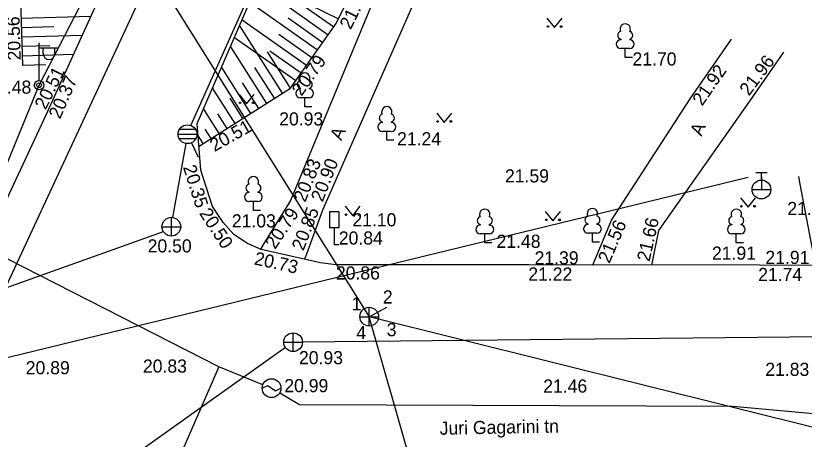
# Model space of a CAD drawing. Extents: x 714391 to 714584, y 6589993 to 6590151.
# Drawn here: x 714448.93 to 714490.89, y 6590092.2 to 6590114.75 of the extents above; entities that cross this region are included whole.
import ezdxf

# ---------------------------------------------------------------- set-up
doc = ezdxf.new("R2010")
doc.units = 0
for name, color, linetype in [('HALJASTUS', 7, 'Continuous'), ('HOONE', 7, 'Continuous'), ('KKAEV', 7, 'Continuous'), ('KORGUS', 7, 'Continuous'), ('KTRASS', 7, 'Continuous'), ('LIIKLUS', 7, 'Continuous'), ('MPKAABEL', 7, 'Continuous'), ('POST', 7, 'Continuous'), ('PUU', 7, 'Continuous'), ('RELJEEF', 7, 'Continuous'), ('SITRASS', 7, 'Continuous'), ('SKKAEV', 7, 'Continuous'), ('SKTRASS', 7, 'Continuous'), ('TEE', 7, 'Continuous'), ('TORU NR', 7, 'Continuous'), ('VKAEV', 7, 'Continuous'), ('VTRASS', 7, 'Continuous')]:
    doc.layers.add(name, color=color, linetype=linetype)

msp = doc.modelspace()

# ---------------------------------------------------------------- linework, layer by layer
at = {"layer": 'HALJASTUS'}
for p, q in [((714477.203, 6590114.63), (714477.608, 6590114.125)), ((714477.608, 6590114.125), (714478.003, 6590114.63)), ((714460.812, 6590110.566), (714461.217, 6590110.061)), ((714461.217, 6590110.061), (714461.612, 6590110.566)), ((714471.333, 6590109.573), (714471.738, 6590109.068)), ((714471.738, 6590109.068), (714472.133, 6590109.573)), ((714487.498, 6590105.058), (714487.903, 6590104.553)), ((714487.903, 6590104.553), (714488.298, 6590105.058)), ((714466.456, 6590104.606), (714466.861, 6590104.101)), ((714466.861, 6590104.101), (714467.256, 6590104.606)), ((714477.113, 6590104.335), (714477.518, 6590103.83)), ((714477.518, 6590103.83), (714477.913, 6590104.335))]:
    msp.add_line(p, q, dxfattribs=at)
for centre, radius in [((714477.255, 6590114.18), 0.0428), ((714477.955, 6590114.18), 0.0452), ((714460.864, 6590110.117), 0.0428), ((714461.564, 6590110.117), 0.0452), ((714471.385, 6590109.123), 0.0428), ((714472.085, 6590109.123), 0.0452), ((714487.55, 6590104.608), 0.0428), ((714488.25, 6590104.608), 0.0452), ((714466.508, 6590104.156), 0.0428), ((714467.208, 6590104.156), 0.0452), ((714477.165, 6590103.885), 0.0428), ((714477.865, 6590103.885), 0.0452)]:
    msp.add_circle(centre, radius, dxfattribs=at)
at = {"layer": 'HOONE'}
for p, q in [((714462.045, 6590094.919), (714462.345, 6590095.069)), ((714462.345, 6590095.069), (714462.745, 6590094.769)), ((714462.745, 6590094.769), (714463.045, 6590094.919))]:
    msp.add_line(p, q, dxfattribs=at)
for points in [[(714462.081, 6590095.105), (714459.73, 6590096.05), (714433.74, 6590109.31), (714441.36, 6590125.77), (714449.34, 6590143.41), (714452.652, 6590151.075)], [(714459.73, 6590096.05), (714450.33, 6590074.44), (714440.46, 6590052.39), (714432.7, 6590035.24), (714421.56, 6590009.98), (714417.1, 6590000.12), (714413.783, 6589992.711)], [(714462.976, 6590094.666), (714464.039, 6590094.043), (714487.101, 6590093.963), (714494.525, 6590093.286), (714520.217, 6590091.196), (714543.829, 6590084.007)]]:
    msp.add_lwpolyline(points, dxfattribs=at)
msp.add_circle((714462.545, 6590094.919), 0.5, dxfattribs=at)
at = {"layer": 'KKAEV'}
for p, q in [((714457.21, 6590103.019), (714457.21, 6590104.019)), ((714456.71, 6590103.519), (714457.71, 6590103.519)), ((714467.741, 6590098.226), (714467.741, 6590099.226)), ((714467.241, 6590098.726), (714468.241, 6590098.726)), ((714463.689, 6590096.867), (714463.689, 6590097.867)), ((714463.189, 6590097.367), (714464.189, 6590097.367))]:
    msp.add_line(p, q, dxfattribs=at)
for centre in [(714457.21, 6590103.519), (714467.741, 6590098.726), (714463.689, 6590097.367)]:
    msp.add_circle(centre, 0.5, dxfattribs=at)
at = {"layer": 'KTRASS'}
for p, q in [((714455.022, 6590119.06), (714467.741, 6590098.726)), ((714467.741, 6590098.726), (714468.676, 6590099.236)), ((714475.96, 6590069.911), (714467.741, 6590098.726)), ((714505.642, 6590089.275), (714467.741, 6590098.726))]:
    msp.add_line(p, q, dxfattribs=at)
at = {"layer": 'LIIKLUS'}
for p, q in [((714465.62, 6590104.311), (714465.62, 6590103.461)), ((714466.12, 6590104.311), (714465.62, 6590104.311)), ((714466.12, 6590104.311), (714466.12, 6590103.461)), ((714466.12, 6590103.461), (714465.62, 6590103.461)), ((714465.87, 6590103.461), (714465.87, 6590102.561)), ((714466.12, 6590102.561), (714465.87, 6590102.561))]:
    msp.add_line(p, q, dxfattribs=at)
at = {"layer": 'MPKAABEL'}
msp.add_lwpolyline([(714394.611, 6589992.711), (714400.19, 6590004.938), (714412.114, 6590031.265), (714423.696, 6590056.183), (714434.84, 6590082.35), (714435.599, 6590083.495), (714435.59, 6590083.97), (714441.1, 6590097.08), (714442.02, 6590098.72), (714442.75, 6590099.35), (714444.22, 6590100.41), (714445.54, 6590101.3), (714446.63, 6590102.41), (714450.168, 6590111.053), (714453.153, 6590116.846), (714463.66, 6590139.57), (714466.53, 6590147), (714468.444, 6590151.075)], dxfattribs=at)
at = {"layer": 'POST'}
for p, q in [((714450.168, 6590111.303), (714450.168, 6590113.303)), ((714450.168, 6590113.053), (714451.168, 6590113.053)), ((714450.395, 6590112.732), (714450.395, 6590113.053)), ((714451.007, 6590112.732), (714451.007, 6590113.053)), ((714450.168, 6590111.053), (714450.168, 6590111.053))]:
    msp.add_line(p, q, dxfattribs=at)
for radius in [0.25, 0.127]:
    msp.add_circle((714450.168, 6590111.053), radius, dxfattribs=at)
msp.add_arc((714450.701, 6590112.732), 0.306, 180, 0, dxfattribs=at)
at = {"layer": 'PUU'}
for p, q in [((714481.126, 6590113.508), (714481.126, 6590113.478)), ((714481.606, 6590113.508), (714481.606, 6590113.478)), ((714481.606, 6590113.003), (714481.126, 6590113.003)), ((714481.366, 6590112.528), (714481.366, 6590113.003)), ((714481.746, 6590112.528), (714481.366, 6590112.528)), ((714464.069, 6590110.889), (714464.069, 6590110.859)), ((714464.549, 6590110.889), (714464.549, 6590110.859)), ((714464.549, 6590110.384), (714464.069, 6590110.384)), ((714464.309, 6590109.909), (714464.309, 6590110.384)), ((714464.689, 6590109.909), (714464.309, 6590109.909)), ((714468.438, 6590109.099), (714468.438, 6590109.069)), ((714468.918, 6590109.099), (714468.918, 6590109.069)), ((714468.918, 6590108.594), (714468.438, 6590108.594)), ((714468.678, 6590108.119), (714468.678, 6590108.594)), ((714469.058, 6590108.119), (714468.678, 6590108.119)), ((714461.337, 6590105.369), (714461.337, 6590105.339)), ((714461.817, 6590105.369), (714461.817, 6590105.339)), ((714461.817, 6590104.864), (714461.337, 6590104.864)), ((714461.577, 6590104.389), (714461.577, 6590104.864)), ((714461.957, 6590104.389), (714461.577, 6590104.389)), ((714473.652, 6590103.639), (714473.652, 6590103.609)), ((714474.132, 6590103.639), (714474.132, 6590103.609)), ((714479.381, 6590103.674), (714479.381, 6590103.644)), ((714479.861, 6590103.674), (714479.861, 6590103.644)), ((714487.037, 6590103.641), (714487.037, 6590103.611)), ((714487.517, 6590103.641), (714487.517, 6590103.611)), ((714474.132, 6590103.134), (714473.652, 6590103.134)), ((714473.892, 6590102.659), (714473.892, 6590103.134)), ((714479.861, 6590103.169), (714479.381, 6590103.169)), ((714479.621, 6590102.694), (714479.621, 6590103.169)), ((714487.517, 6590103.136), (714487.037, 6590103.136)), ((714487.277, 6590102.661), (714487.277, 6590103.136)), ((714474.272, 6590102.659), (714473.892, 6590102.659)), ((714480.001, 6590102.694), (714479.621, 6590102.694)), ((714487.657, 6590102.661), (714487.277, 6590102.661))]:
    msp.add_line(p, q, dxfattribs=at)
for centre, radius, start, end in [((714481.366, 6590114.048), 0.277, 332.5799, 207.4201), ((714481.176, 6590113.715), 0.212, 105.2441, 257.079), ((714481.556, 6590113.715), 0.212, 282.921, 74.7559), ((714481.128, 6590113.24), 0.237, 90, 270), ((714481.603, 6590113.24), 0.237, 270, 90), ((714464.309, 6590111.429), 0.277, 332.5799, 207.4201), ((714464.119, 6590111.096), 0.212, 105.2441, 257.079), ((714464.499, 6590111.096), 0.212, 282.921, 74.7559), ((714464.071, 6590110.622), 0.237, 90, 270), ((714464.546, 6590110.622), 0.237, 270, 90), ((714468.488, 6590109.306), 0.212, 105.2441, 257.079), ((714468.678, 6590109.639), 0.277, 332.5799, 207.4201), ((714468.868, 6590109.306), 0.212, 282.921, 74.7559), ((714468.441, 6590108.832), 0.237, 90, 270), ((714468.916, 6590108.832), 0.237, 270, 90), ((714461.577, 6590105.909), 0.277, 332.5799, 207.4201), ((714461.387, 6590105.577), 0.212, 105.2441, 257.079), ((714461.767, 6590105.577), 0.212, 282.921, 74.7559), ((714461.34, 6590105.102), 0.237, 90, 270), ((714461.815, 6590105.102), 0.237, 270, 90), ((714479.621, 6590104.214), 0.277, 332.5799, 207.4201), ((714473.892, 6590104.179), 0.277, 332.5799, 207.4201), ((714479.431, 6590103.882), 0.212, 105.2441, 257.079), ((714479.811, 6590103.882), 0.212, 282.921, 74.7559), ((714487.277, 6590104.181), 0.277, 332.5799, 207.4201), ((714473.702, 6590103.846), 0.212, 105.2441, 257.079), ((714474.082, 6590103.846), 0.212, 282.921, 74.7559), ((714479.383, 6590103.406), 0.237, 90, 270), ((714479.858, 6590103.406), 0.237, 270, 90), ((714487.087, 6590103.849), 0.212, 105.2441, 257.079), ((714487.467, 6590103.849), 0.212, 282.921, 74.7559), ((714473.654, 6590103.372), 0.237, 90, 270), ((714474.129, 6590103.372), 0.237, 270, 90), ((714487.039, 6590103.374), 0.237, 90, 270), ((714487.514, 6590103.374), 0.237, 270, 90)]:
    msp.add_arc(centre, radius, start, end, dxfattribs=at)
at = {"layer": 'RELJEEF'}
for p, q in [((714461.896, 6590116.667), (714466.103, 6590114.584)), ((714461.788, 6590116.417), (714465.561, 6590113.746)), ((714461.383, 6590115.479), (714464.984, 6590112.93)), ((714463.921, 6590115.52), (714465.85, 6590114.155)), ((714452.921, 6590114.719), (714449.208, 6590114.609)), ((714463.429, 6590114.643), (714465.273, 6590113.338)), ((714450.957, 6590114.161), (714449.222, 6590114.109)), ((714460.834, 6590114.209), (714463.113, 6590110.626)), ((714460.977, 6590114.54), (714464.406, 6590112.114)), ((714462.937, 6590113.766), (714464.695, 6590112.522)), ((714452.462, 6590113.705), (714449.237, 6590113.609)), ((714460.572, 6590113.602), (714463.829, 6590111.298)), ((714450.742, 6590113.154), (714449.252, 6590113.11)), ((714460.354, 6590113.1), (714462.269, 6590110.089)), ((714462.446, 6590112.889), (714464.117, 6590111.706)), ((714452.002, 6590112.691), (714449.267, 6590112.61)), ((714462.304, 6590112.829), (714463.535, 6590110.894)), ((714450.527, 6590112.147), (714449.282, 6590112.11)), ((714459.875, 6590111.991), (714461.426, 6590109.553)), ((714461.643, 6590112.006), (714462.691, 6590110.358)), ((714459.395, 6590110.882), (714460.582, 6590109.016)), ((714460.981, 6590111.183), (714461.847, 6590109.821)), ((714460.319, 6590110.36), (714461.004, 6590109.284)), ((714458.915, 6590109.773), (714459.738, 6590108.479)), ((714459.658, 6590109.537), (714460.16, 6590108.748)), ((714458.996, 6590108.714), (714459.316, 6590108.211)), ((714458.643, 6590108.338), (714458.894, 6590107.943))]:
    msp.add_line(p, q, dxfattribs=at)
for points in [[(714461.322, 6590149.285), (714459.685, 6590146.474), (714455.021, 6590135.724), (714449.023, 6590120.812), (714449.282, 6590112.11)], [(714458.683, 6590107.808), (714459.134, 6590108.095), (714463.55, 6590110.904), (714465.985, 6590114.345), (714472.574, 6590127.656), (714478.445, 6590140.562)]]:
    msp.add_lwpolyline(points, dxfattribs=at)
at = {"layer": 'SITRASS'}
msp.add_line((714445.318, 6590093.669), (714471.983, 6590151.075), dxfattribs=at)
at = {"layer": 'SKKAEV'}
for p, q in [((714458.502, 6590108.694), (714457.642, 6590108.694)), ((714457.572, 6590108.444), (714458.572, 6590108.444)), ((714458.502, 6590108.194), (714457.642, 6590108.194))]:
    msp.add_line(p, q, dxfattribs=at)
msp.add_circle((714458.072, 6590108.444), 0.5, dxfattribs=at)
at = {"layer": 'SKTRASS'}
for p, q in [((714458.254, 6590108.91), (714474.359, 6590144.932)), ((714457.983, 6590107.952), (714457.267, 6590104.016)), ((714458.285, 6590107.992), (714458.645, 6590107.226)), ((714442.481, 6590098.162), (714456.8, 6590103.262)), ((714497.432, 6590097.718), (714464.189, 6590097.372)), ((714463.282, 6590097.077), (714449.797, 6590087.49))]:
    msp.add_line(p, q, dxfattribs=at)
at = {"layer": 'TEE'}
for points in [[(714450.542, 6590109.47), (714454.553, 6590118.32), (714462.112, 6590135.302), (714467.698, 6590147.41), (714469.311, 6590151.075)], [(714583.92, 6590101.143), (714565.419, 6590101.225), (714549.748, 6590101.3), (714530.696, 6590101.382), (714516.957, 6590101.382), (714497.906, 6590101.442), (714488.527, 6590101.467), (714476.238, 6590101.479), (714465.964, 6590101.492), (714465.149, 6590101.593), (714461.989, 6590102.308), (714461.271, 6590102.628), (714460.534, 6590103.105), (714459.97, 6590103.737), (714459.406, 6590104.596), (714458.782, 6590106.528), (714458.59, 6590109.02), (714468.756, 6590132.53), (714474.437, 6590144.828), (714474.939, 6590145.152), (714475.17, 6590145.792), (714474.999, 6590146.077), (714477.095, 6590151.075)], [(714483.807, 6590151.075), (714479.211, 6590140.446), (714473.212, 6590126.702), (714468.119, 6590115.935), (714463.556, 6590104.916), (714462.138, 6590102.626), (714461.947, 6590102.318)], [(714485.932, 6590151.075), (714482.73, 6590143.88), (714480.61, 6590139.609), (714475.962, 6590129.206), (714470.061, 6590115.343), (714465.263, 6590104.4), (714464.405, 6590102.057), (714464.305, 6590101.784)], [(714479.649, 6590101.476), (714479.721, 6590101.65), (714480.632, 6590103.871), (714484.831, 6590110.335), (714487.017, 6590113.499)], [(714489.794, 6590112.821), (714487.976, 6590110.21), (714483.131, 6590103.313), (714482.799, 6590101.643), (714482.765, 6590101.473)], [(714442.53, 6590099.149), (714444.488, 6590099.946), (714446.305, 6590101.019), (714446.966, 6590101.823), (714450.542, 6590109.47)]]:
    msp.add_lwpolyline(points, dxfattribs=at)
at = {"layer": 'VKAEV'}
for p, q in [((714488.314, 6590106.4), (714488.914, 6590106.4)), ((714488.614, 6590106), (714488.614, 6590106.4)), ((714488.114, 6590105.5), (714489.114, 6590105.5))]:
    msp.add_line(p, q, dxfattribs=at)
msp.add_circle((714488.614, 6590105.5), 0.5, dxfattribs=at)
at = {"layer": 'VTRASS'}
for p, q in [((714488.619, 6590106.169), (714488.614, 6590105.5)), ((714442.577, 6590095.127), (714487.91, 6590106.151))]:
    msp.add_line(p, q, dxfattribs=at)
msp.add_lwpolyline([(714490.586, 6590106.186), (714490.652, 6590105.776), (714491.439, 6590101.677), (714493.283, 6590096.028), (714496.505, 6590087.34)], dxfattribs=at)

# ---------------------------------------------------------------- texts
at = {"layer": 'KORGUS'}
for s, rotation, p in [('21.01', 63.5437, (714466.755, 6590113.979)), ('20.56', 91.7899, (714449.201, 6590112.387)), ('20.79', 54.8458, (714464.137, 6590110.433)), ('21.96', 53.1301, (714487.951, 6590110.446)), ('21.92', 55.1543, (714485.46, 6590109.91)), ('20.51', 63.6669, (714450.523, 6590109.711)), ('20.37', 66.4477, (714451.289, 6590109.215)), ('20.51', 29.421, (714459.51, 6590107.494)), ('20.83', 68.3742, (714464.337, 6590104.784)), ('20.90', 68.5631, (714465.259, 6590104.798)), ('20.35', 287.5783, (714457.822, 6590106.693)), ('20.50', 303.2317, (714458.671, 6590104.23)), ('20.79', 56.0989, (714462.73, 6590102.277)), ('20.85', 68.725, (714464.24, 6590102.2)), ('21.56', 66.7474, (714480.526, 6590101.527)), ('21.66', 77.417, (714482.659, 6590101.627)), ('20.73', 347.5567, (714461.58, 6590101.514))]:
    msp.add_text(s, height=0.7, rotation=rotation, dxfattribs=at).set_placement(p)
for s, p in [('21.70', (714481.754, 6590112.103)), ('20.48', (714447.415, 6590110.603)), ('20.93', (714462.951, 6590108.91)), ('21.24', (714469.224, 6590107.852)), ('21.59', (714474.967, 6590105.875)), ('21.98', (714489.993, 6590104.138)), ('21.03', (714460.43, 6590103.479)), ('21.10', (714466.845, 6590103.536)), ('20.84', (714466.124, 6590102.568)), ('20.50', (714455.95, 6590102.146)), ('21.48', (714474.517, 6590102.392)), ('21.91', (714485.983, 6590101.762)), ('21.39', (714476.544, 6590101.509)), ('21.91', (714488.827, 6590101.533)), ('20.86', (714465.968, 6590100.706)), ('21.22', (714476.208, 6590100.648)), ('21.74', (714488.441, 6590100.625)), ('20.93', (714464.003, 6590096.194)), ('20.89', (714449.462, 6590095.658)), ('20.83', (714455.699, 6590095.746)), ('21.83', (714488.82, 6590095.571)), ('20.99', (714463.222, 6590094.705)), ('21.46', (714477.001, 6590094.682))]:
    msp.add_text(s, height=0.7, dxfattribs=at).set_placement(p)
at = {"layer": 'TEE'}
for s, rotation, p in [('A', 66.1941, (714466.261, 6590108.063)), ('A', 67.1094, (714485.427, 6590108.302)), ('Juri Gagarini tn', 1.1152, (714471.498, 6590092.433))]:
    msp.add_text(s, height=0.7, rotation=rotation, dxfattribs=at).set_placement(p)
at = {"layer": 'TORU NR'}
for s, p in [('2', (714468.468, 6590099.427)), ('1', (714466.805, 6590099.066)), ('4', (714467.056, 6590097.529)), ('3', (714468.672, 6590097.686))]:
    msp.add_text(s, height=0.7, dxfattribs=at).set_placement(p)

doc.saveas('drawing.dxf')
